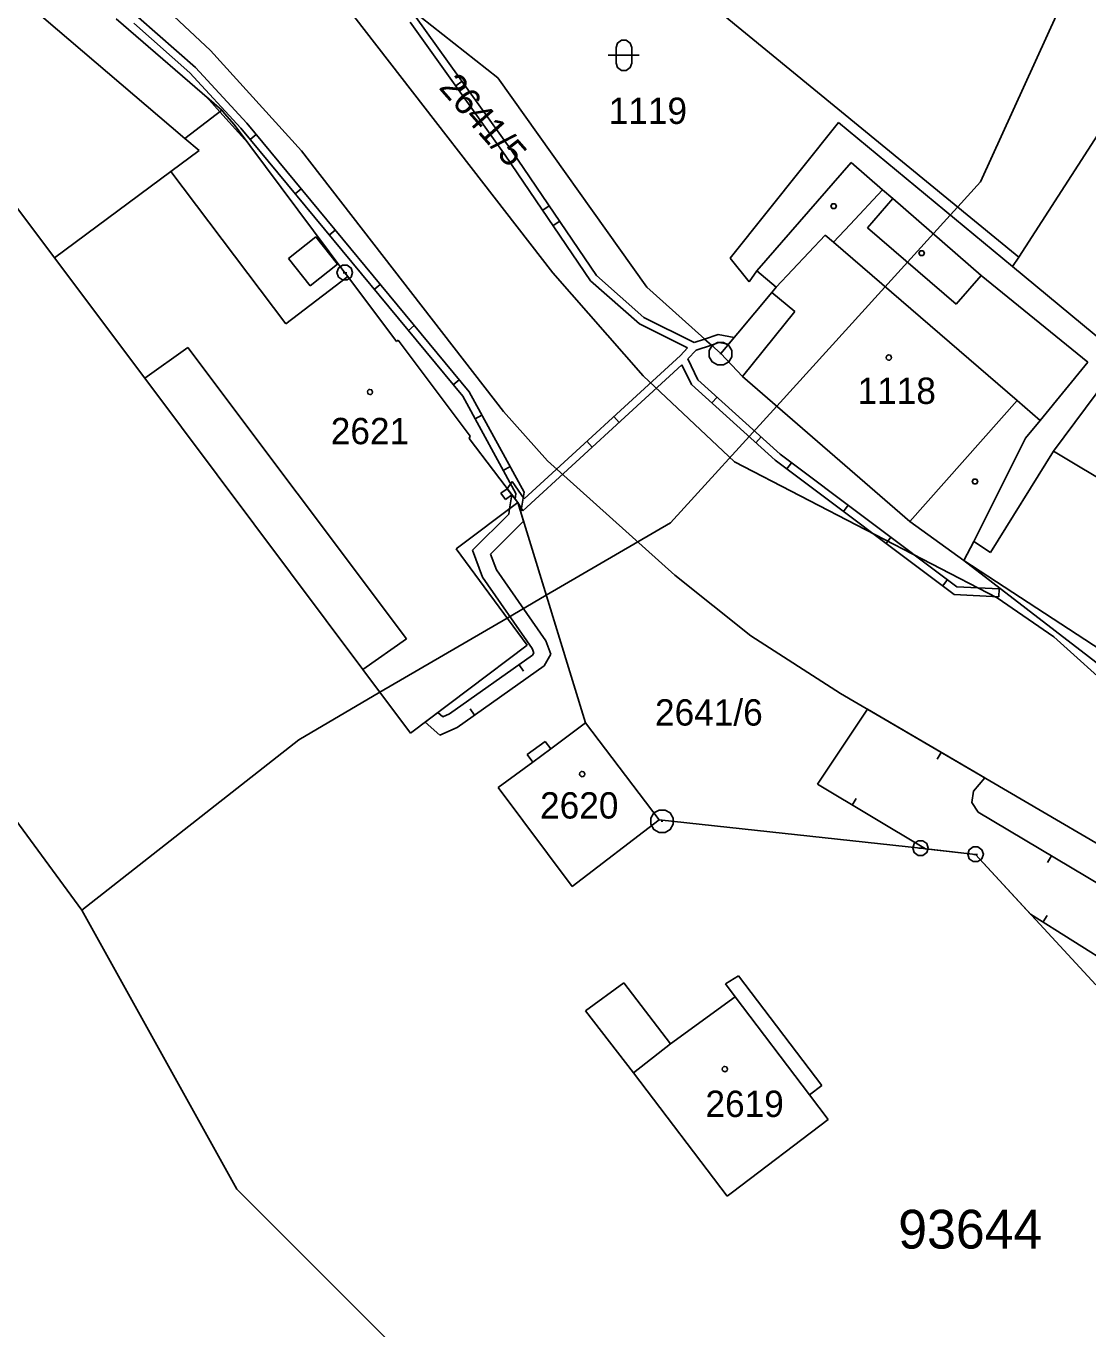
# Model space of a CAD drawing. Extents: x -806774 to -803680, y -1151731 to -1150053.
# Drawn here: x -804078.6 to -804010.1, y -1150277.5 to -1150193.4 of the extents above; entities that cross this region are included whole.
import ezdxf

# ---------------------------------------------------------------- set-up
doc = ezdxf.new("R2010")
doc.units = 0
for name, color, linetype in [('1', 7, 'Continuous'), ('11', 7, 'Continuous'), ('12', 7, 'Continuous'), ('13', 7, 'Continuous'), ('2', 7, 'Continuous'), ('3', 7, 'Continuous'), ('4', 7, 'Continuous'), ('5', 7, 'Continuous'), ('8', 7, 'Continuous')]:
    doc.layers.add(name, color=color, linetype=linetype)

msp = doc.modelspace()

# ---------------------------------------------------------------- linework, layer by layer
at = {"layer": '1'}
for p, q in [((-804038.18, -1150188.96), (-804014.54, -1150208.35)), ((-804079.56, -1150191.12), (-804068.34, -1150200.69)), ((-804066.7, -1150195.01), (-804070.61, -1150191.34)), ((-804054.55, -1150191.72), (-804048.14, -1150196.79)), ((-804065.96, -1150198.88), (-804072.79, -1150192.97)), ((-804057.45, -1150192.8), (-804044.6, -1150209.37)), ((-804005.52, -1150194.37), (-804014.54, -1150208.35)), ((-804060.81, -1150201.5), (-804066.7, -1150195.01)), ((-804048.14, -1150196.79), (-804038.53, -1150210.29)), ((-804068.34, -1150200.69), (-804065.96, -1150198.88)), ((-804065.78, -1150199.08), (-804065.96, -1150198.88)), ((-804065.78, -1150199.08), (-804065.16, -1150199.8)), ((-804065.16, -1150199.8), (-804058.02, -1150209.36)), ((-804033.15, -1150208.42), (-804026.17, -1150199.66)), ((-804026.17, -1150199.66), (-804014.94, -1150208.97)), ((-804082.27, -1150201.05), (-804076.76, -1150208.41)), ((-804067.42, -1150201.47), (-804068.34, -1150200.69)), ((-804069.26, -1150202.82), (-804067.42, -1150201.47)), ((-804047.79, -1150218.32), (-804060.81, -1150201.5)), ((-804076.76, -1150208.41), (-804069.26, -1150202.82)), ((-804070.92, -1150216.16), (-804076.76, -1150208.41)), ((-804031.94, -1150209.94), (-804033.15, -1150208.42)), ((-804014.94, -1150208.97), (-804014.54, -1150208.35)), ((-804058.02, -1150209.36), (-804057.84, -1150209.6)), ((-804057.84, -1150209.6), (-804054.7, -1150213.8)), ((-804044.6, -1150209.37), (-804038.78, -1150216.01)), ((-804031.44, -1150209.25), (-804031.94, -1150209.94)), ((-804030.19, -1150210.3), (-804031.44, -1150209.25)), ((-804014.94, -1150208.97), (-804007.83, -1150214.86)), ((-804038.53, -1150210.29), (-804033.76, -1150214.58)), ((-804030.19, -1150210.3), (-804030.47, -1150210.63)), ((-804033.76, -1150214.58), (-804030.47, -1150210.63)), ((-804054.7, -1150213.8), (-804054.58, -1150213.71)), ((-804054.58, -1150213.71), (-804049.93, -1150219.91)), ((-804033.76, -1150214.58), (-804032.36, -1150216.05)), ((-804007.83, -1150214.86), (-804012.29, -1150220.87)), ((-804056.87, -1150234.96), (-804070.92, -1150216.16)), ((-804038.78, -1150216.01), (-804032.88, -1150221.57)), ((-804021.57, -1150225.42), (-804032.36, -1150216.05)), ((-804044.95, -1150221.51), (-804047.79, -1150218.32)), ((-804049.93, -1150219.91), (-804050.01, -1150220.06)), ((-804050.01, -1150220.06), (-804046.86, -1150224.2)), ((-804012.29, -1150220.87), (-804016.36, -1150227.42)), ((-803996.21, -1150230.54), (-804012.29, -1150220.87)), ((-804036.73, -1150228.89), (-804044.95, -1150221.51)), ((-804032.88, -1150221.57), (-804015.93, -1150230.34)), ((-804050.84, -1150227.18), (-804046.86, -1150224.2)), ((-804046.86, -1150224.2), (-804042.5, -1150238.42)), ((-804021.57, -1150225.42), (-804018.08, -1150227.93)), ((-804046.26, -1150233.41), (-804050.84, -1150227.18)), ((-804018.08, -1150227.93), (-804017.43, -1150226.7)), ((-804017.43, -1150226.7), (-804016.36, -1150227.42)), ((-804002.08, -1150240.27), (-804018.08, -1150227.93)), ((-804031.83, -1150232.79), (-804036.73, -1150228.89)), ((-804015.93, -1150230.34), (-804012.27, -1150232.87)), ((-804026.04, -1150236.52), (-804031.83, -1150232.79)), ((-804012.27, -1150232.87), (-804002.98, -1150241.24)), ((-804053.79, -1150239.08), (-804046.26, -1150233.41)), ((-804053.79, -1150239.08), (-804056.87, -1150234.96)), ((-804001.67, -1150250.78), (-804026.04, -1150236.52)), ((-804042.5, -1150238.42), (-804044.74, -1150240.08)), ((-804042.5, -1150238.42), (-804037.73, -1150244.68)), ((-804045.09, -1150239.61), (-804046.26, -1150240.46)), ((-804044.74, -1150240.08), (-804045.09, -1150239.61)), ((-804046.26, -1150240.46), (-804045.9, -1150240.94)), ((-804045.9, -1150240.94), (-804048.13, -1150242.59)), ((-804043.35, -1150248.97), (-804048.13, -1150242.59)), ((-804037.73, -1150244.68), (-804043.35, -1150248.97)), ((-804020.87, -1150246.51), (-804037.73, -1150244.68)), ((-804017.32, -1150246.9), (-804020.87, -1150246.51)), ((-804017.32, -1150246.9), (-804009.55, -1150255.32)), ((-804033.46, -1150255.26), (-804032.63, -1150254.75)), ((-804032.63, -1150254.75), (-804027.25, -1150261.82)), ((-804042.49, -1150256.99), (-804040.01, -1150255.2)), ((-804040.01, -1150255.2), (-804037.01, -1150259.13)), ((-804032.83, -1150256.09), (-804033.46, -1150255.26)), ((-804037.01, -1150259.13), (-804032.83, -1150256.09)), ((-804039.39, -1150261.01), (-804042.49, -1150256.99)), ((-804033.36, -1150268.97), (-804039.39, -1150261.01)), ((-804028.04, -1150262.42), (-804027.25, -1150261.82)), ((-804026.84, -1150264.01), (-804028.04, -1150262.42)), ((-804033, -1150268.7), (-804026.84, -1150264.01)), ((-804033, -1150268.7), (-804033.36, -1150268.97))]:
    msp.add_line(p, q, dxfattribs=at)
at = {"layer": '11'}
for points in [[(-804075, -1150250.5), (-804061, -1150239.5), (-804055.76, -1150236.44), (-804047.55, -1150231.65), (-804045.03, -1150230.18), (-804037, -1150225.5), (-804030.15, -1150217.97), (-804018.95, -1150205.65), (-804018.47, -1150205.12), (-804017, -1150203.5), (-804007.8, -1150183.27), (-804007, -1150181.5), (-804006.2, -1150179.38), (-804002.16, -1150168.59), (-804001.72, -1150167.41), (-804001, -1150165.5), (-803996.39, -1150161.1), (-803995.83, -1150160.56), (-803991.51, -1150156.45), (-803989.423, -1150154.449)], [(-804075, -1150250.5), (-804130.24, -1150175.18), (-804140.05, -1150161.79), (-804142.886, -1150157.919)], [(-804025, -1150309.5), (-804033, -1150300.5), (-804065, -1150268.5), (-804075, -1150250.5)]]:
    msp.add_lwpolyline(points, dxfattribs=at)
at = {"layer": '12'}
for p, q in [((-804076.76, -1150208.41), (-804069.26, -1150202.82)), ((-804069.26, -1150202.82), (-804061.84, -1150212.67)), ((-804030.19, -1150210.3), (-804027.02, -1150206.93)), ((-804027.02, -1150206.93), (-804026.48, -1150207.39)), ((-804026.48, -1150207.39), (-804014.63, -1150217.6)), ((-804070.92, -1150216.16), (-804076.76, -1150208.41)), ((-804061.84, -1150212.67), (-804057.84, -1150209.6)), ((-804057.84, -1150209.6), (-804054.7, -1150213.8)), ((-804030.19, -1150210.3), (-804030.47, -1150210.63)), ((-804030.47, -1150210.63), (-804028.99, -1150211.86)), ((-804028.99, -1150211.86), (-804032.36, -1150216.05)), ((-804054.7, -1150213.8), (-804054.58, -1150213.71)), ((-804054.58, -1150213.71), (-804049.93, -1150219.91)), ((-804070.92, -1150216.16), (-804068.15, -1150214.19)), ((-804068.15, -1150214.19), (-804054.05, -1150233)), ((-804021.57, -1150225.42), (-804032.36, -1150216.05)), ((-804021.57, -1150225.42), (-804014.63, -1150217.6)), ((-804049.93, -1150219.91), (-804050.01, -1150220.06)), ((-804050.01, -1150220.06), (-804046.86, -1150224.2)), ((-804050.84, -1150227.18), (-804046.86, -1150224.2)), ((-804046.26, -1150233.41), (-804050.84, -1150227.18)), ((-804054.05, -1150233), (-804056.87, -1150234.96)), ((-804053.79, -1150239.08), (-804046.26, -1150233.41)), ((-804053.79, -1150239.08), (-804056.87, -1150234.96)), ((-804042.5, -1150238.42), (-804044.74, -1150240.08)), ((-804042.5, -1150238.42), (-804037.73, -1150244.68)), ((-804044.74, -1150240.08), (-804045.9, -1150240.94)), ((-804045.9, -1150240.94), (-804048.13, -1150242.59)), ((-804043.35, -1150248.97), (-804048.13, -1150242.59)), ((-804037.73, -1150244.68), (-804043.35, -1150248.97)), ((-804037.01, -1150259.13), (-804032.83, -1150256.09)), ((-804032.83, -1150256.09), (-804028.04, -1150262.42)), ((-804039.39, -1150261.01), (-804037.01, -1150259.13)), ((-804033.36, -1150268.97), (-804039.39, -1150261.01)), ((-804026.84, -1150264.01), (-804028.04, -1150262.42)), ((-804033, -1150268.7), (-804026.84, -1150264.01)), ((-804033, -1150268.7), (-804033.36, -1150268.97))]:
    msp.add_line(p, q, dxfattribs=at)
at = {"layer": '13'}
for p, q in [((-804068.02, -1150196.47), (-804071.65, -1150193.26)), ((-804071.33, -1150192.88), (-804067.66, -1150196.11)), ((-804047.67, -1150201.77), (-804053.8, -1150193.2)), ((-804053.42, -1150192.88), (-804047.25, -1150201.49)), ((-804067.66, -1150196.11), (-804064.35, -1150199.72)), ((-804064.73, -1150200.03), (-804068.02, -1150196.47)), ((-804050.87, -1150197.297), (-804050.463, -1150197.006)), ((-804050.216, -1150197.351), (-804050.623, -1150197.642)), ((-804066.96, -1150198.01), (-804065.96, -1150198.88)), ((-804066.09, -1150198.98), (-804066.96, -1150198.01)), ((-804064.28, -1150200.98), (-804066.09, -1150198.98)), ((-804065.96, -1150198.88), (-804065.78, -1150199.08)), ((-804065.78, -1150199.08), (-804065.16, -1150199.8)), ((-804065.16, -1150199.8), (-804064.28, -1150200.98)), ((-804050.42, -1150217.33), (-804064.73, -1150200.03)), ((-804064.35, -1150199.72), (-804050, -1150217.05)), ((-804064.124, -1150200.763), (-804063.738, -1150200.444)), ((-804042.16, -1150209.88), (-804047.67, -1150201.77)), ((-804047.25, -1150201.49), (-804041.78, -1150209.54)), ((-804060.842, -1150203.956), (-804061.227, -1150204.275)), ((-804045.251, -1150205.331), (-804044.837, -1150205.049)), ((-804044.159, -1150206.039), (-804044.572, -1150206.32)), ((-804059.025, -1150206.928), (-804058.639, -1150206.609)), ((-804041.78, -1150209.54), (-804038.72, -1150212.25)), ((-804055.74, -1150210.118), (-804056.125, -1150210.437)), ((-804039, -1150212.67), (-804042.16, -1150209.88)), ((-804053.926, -1150213.092), (-804053.54, -1150212.773)), ((-804035.91, -1150214.21), (-804039, -1150212.67)), ((-804038.72, -1150212.25), (-804035.48, -1150213.86)), ((-804035.48, -1150213.86), (-804034.81, -1150213.64)), ((-804034.81, -1150213.64), (-804033.93, -1150213.35)), ((-804034.81, -1150213.64), (-804034.37, -1150214.03)), ((-804034.37, -1150214.03), (-804034.81, -1150213.64)), ((-804033.93, -1150213.35), (-804032.9, -1150213.54)), ((-804032.9, -1150213.54), (-804033.26, -1150213.98)), ((-804036.37, -1150214.71), (-804035.91, -1150214.21)), ((-804035.36, -1150214.35), (-804035.89, -1150214.93)), ((-804034.37, -1150214.03), (-804035.36, -1150214.35)), ((-804033.89, -1150213.87), (-804034.37, -1150214.03)), ((-804033.26, -1150213.98), (-804033.89, -1150213.87)), ((-804036.27, -1150215.3), (-804046.53, -1150224.72)), ((-804046.45, -1150223.96), (-804036.37, -1150214.71)), ((-804035.65, -1150216.58), (-804036.27, -1150215.3)), ((-804035.89, -1150214.93), (-804035.25, -1150216.28)), ((-804050.638, -1150216.28), (-804051.023, -1150216.599)), ((-804035.25, -1150216.28), (-804029.94, -1150221.07)), ((-804050, -1150217.05), (-804046.46, -1150223.53)), ((-804030.26, -1150221.45), (-804035.65, -1150216.58)), ((-804046.98, -1150223.61), (-804050.42, -1150217.33)), ((-804034.341, -1150217.763), (-804034.006, -1150217.392)), ((-804049.622, -1150218.786), (-804049.184, -1150218.546)), ((-804040.321, -1150219.02), (-804040.659, -1150218.651)), ((-804042.398, -1150220.241), (-804042.06, -1150220.61)), ((-804031.166, -1150219.964), (-804031.501, -1150220.335)), ((-804029.94, -1150221.07), (-804018.52, -1150229.63)), ((-804047.363, -1150221.877), (-804047.802, -1150222.116)), ((-804018.7, -1150230.13), (-804030.26, -1150221.45)), ((-804029.496, -1150222.024), (-804029.195, -1150221.624)), ((-804047.55, -1150223.3), (-804047.23, -1150222.84)), ((-804047.23, -1150222.84), (-804046.45, -1150223.96)), ((-804047.95, -1150223.6), (-804047.55, -1150223.3)), ((-804047.65, -1150224), (-804047.95, -1150223.6)), ((-804047.25, -1150223.69), (-804047.65, -1150224)), ((-804047.25, -1150223.69), (-804047.55, -1150223.3)), ((-804047.55, -1150223.3), (-804047.25, -1150223.69)), ((-804047.39, -1150224.6), (-804047.25, -1150223.69)), ((-804046.86, -1150224.2), (-804047.25, -1150223.69)), ((-804047.25, -1150223.69), (-804046.86, -1150224.2)), ((-804047.04, -1150223.97), (-804046.98, -1150223.61)), ((-804046.46, -1150223.53), (-804046.67, -1150224.82)), ((-804047.45, -1150224.94), (-804047.39, -1150224.6)), ((-804046.86, -1150224.2), (-804047.04, -1150223.97)), ((-804046.53, -1150224.72), (-804046.86, -1150224.2)), ((-804046.67, -1150224.82), (-804046.86, -1150224.2)), ((-804046.86, -1150224.2), (-804046.49, -1150225.4)), ((-804025.539, -1150224.369), (-804025.839, -1150224.769)), ((-804049.79, -1150227.26), (-804047.45, -1150224.94)), ((-804046.49, -1150225.4), (-804048.63, -1150227.52)), ((-804023.098, -1150226.828), (-804022.798, -1150226.428)), ((-804049.13, -1150229), (-804049.79, -1150227.26)), ((-804048.63, -1150227.52), (-804048.24, -1150228.53)), ((-804048.24, -1150228.53), (-804045.05, -1150233.13)), ((-804045.93, -1150233.61), (-804049.13, -1150229)), ((-804019.138, -1150229.167), (-804019.438, -1150229.567)), ((-804018.52, -1150229.63), (-804015.79, -1150229.77)), ((-804015.79, -1150229.77), (-804015.81, -1150230.27)), ((-804015.81, -1150230.27), (-804018.7, -1150230.13)), ((-804045.05, -1150233.13), (-804044.72, -1150233.98)), ((-804045.82, -1150233.9), (-804045.93, -1150233.61)), ((-804045.91, -1150234.04), (-804045.82, -1150233.9)), ((-804044.72, -1150233.98), (-804045.17, -1150234.74)), ((-804051.27, -1150237.84), (-804045.91, -1150234.04)), ((-804045.17, -1150234.74), (-804050.77, -1150238.72)), ((-804046.783, -1150234.659), (-804046.494, -1150235.067)), ((-804051.69, -1150238.03), (-804051.27, -1150237.84)), ((-804049.653, -1150237.926), (-804049.943, -1150237.519)), ((-804027.53, -1150242.37), (-804024.29, -1150237.54)), ((-804024.29, -1150237.54), (-804016.73, -1150241.97)), ((-804051.89, -1150239.2), (-804052.83, -1150238.36)), ((-804050.77, -1150238.72), (-804051.89, -1150239.2)), ((-804019.545, -1150240.321), (-804019.798, -1150240.752)), ((-804020.56, -1150246.54), (-804027.53, -1150242.37)), ((-804016.73, -1150241.97), (-804017.45, -1150242.82)), ((-804017.45, -1150242.82), (-804017.57, -1150243.55)), ((-804025.28, -1150243.716), (-804025.023, -1150243.287)), ((-804017.57, -1150243.55), (-804017.15, -1150244.18)), ((-804017.15, -1150244.18), (-804008.16, -1150249.55)), ((-804017.32, -1150246.9), (-804020.56, -1150246.54)), ((-804013.77, -1150250.75), (-804017.32, -1150246.9)), ((-804012.428, -1150247), (-804012.685, -1150247.43)), ((-804008.32, -1150254.2), (-804013.77, -1150250.75)), ((-804012.967, -1150251.258), (-804012.7, -1150250.836))]:
    msp.add_line(p, q, dxfattribs=at)
msp.add_lwpolyline([(-804052.83, -1150238.36), (-804052.02, -1150237.75), (-804051.69, -1150238.03)], dxfattribs=at)
at = {"layer": '3'}
msp.add_lwpolyline([(-804040.52, -1150194.83), (-804040.42, -1150194.54), (-804040.17, -1150194.36), (-804039.86, -1150194.36), (-804039.61, -1150194.54), (-804039.51, -1150194.83), (-804039.51, -1150195.83), (-804039.61, -1150196.12), (-804039.86, -1150196.3), (-804040.17, -1150196.3), (-804040.42, -1150196.12), (-804040.52, -1150195.83)], close=True, dxfattribs=at)
msp.add_lwpolyline([(-804041.02, -1150195.33), (-804039.75, -1150195.33), (-804039.02, -1150195.33)], dxfattribs=at)
at = {"layer": '4'}
for p, q in [((-804069.26, -1150202.82), (-804061.84, -1150212.67)), ((-804031.44, -1150209.25), (-804025.36, -1150202.24)), ((-804025.36, -1150202.24), (-804023.32, -1150204.02)), ((-804025.41, -1150206.25), (-804023.32, -1150204.02)), ((-804023.32, -1150204.02), (-804022.66, -1150204.58)), ((-804024.3, -1150206.46), (-804022.66, -1150204.58)), ((-804022.66, -1150204.58), (-804016.95, -1150209.55)), ((-804026.48, -1150207.39), (-804025.41, -1150206.25)), ((-804059.9, -1150207.04), (-804061.67, -1150208.45)), ((-804059.9, -1150207.04), (-804058.5, -1150208.8)), ((-804030.19, -1150210.3), (-804027.02, -1150206.93)), ((-804027.02, -1150206.93), (-804026.48, -1150207.39)), ((-804018.57, -1150211.4), (-804024.3, -1150206.46)), ((-804026.48, -1150207.39), (-804014.63, -1150217.6)), ((-804060.27, -1150210.21), (-804061.67, -1150208.45)), ((-804061.84, -1150212.67), (-804057.84, -1150209.6)), ((-804058.5, -1150208.8), (-804060.27, -1150210.21)), ((-804018.57, -1150211.4), (-804016.95, -1150209.55)), ((-804016.95, -1150209.55), (-804010.08, -1150215.13)), ((-804030.47, -1150210.63), (-804028.99, -1150211.86)), ((-804028.99, -1150211.86), (-804032.36, -1150216.05)), ((-804070.92, -1150216.16), (-804068.15, -1150214.19)), ((-804068.15, -1150214.19), (-804054.05, -1150233)), ((-804013.16, -1150218.89), (-804010.08, -1150215.13)), ((-804021.57, -1150225.42), (-804014.63, -1150217.6)), ((-804014.63, -1150217.6), (-804013.16, -1150218.89)), ((-804013.16, -1150218.89), (-804014.1, -1150220.04)), ((-804017.43, -1150226.7), (-804014.1, -1150220.04)), ((-804001.25, -1150238.93), (-804018.08, -1150227.93)), ((-804054.05, -1150233), (-804056.87, -1150234.96)), ((-804044.74, -1150240.08), (-804045.9, -1150240.94)), ((-804032.83, -1150256.09), (-804028.04, -1150262.42)), ((-804039.39, -1150261.01), (-804037.01, -1150259.13))]:
    msp.add_line(p, q, dxfattribs=at)
at = {"layer": '5'}
for points in [[(-804026.39, -1150204.91), (-804026.3, -1150205.06), (-804026.39, -1150205.21), (-804026.57, -1150205.21), (-804026.66, -1150205.06), (-804026.57, -1150204.91)], [(-804020.71, -1150207.95), (-804020.62, -1150208.1), (-804020.71, -1150208.25), (-804020.89, -1150208.25), (-804020.98, -1150208.1), (-804020.89, -1150207.95)], [(-804022.92, -1150214.67), (-804022.82, -1150214.69), (-804022.77, -1150214.78), (-804022.75, -1150214.84), (-804022.77, -1150214.93), (-804022.85, -1150215), (-804022.92, -1150215.01), (-804023.01, -1150214.98), (-804023.07, -1150214.92), (-804023.09, -1150214.84), (-804023.07, -1150214.75), (-804022.99, -1150214.68)], [(-804056.4, -1150216.89), (-804056.3, -1150216.91), (-804056.25, -1150217), (-804056.23, -1150217.06), (-804056.25, -1150217.15), (-804056.33, -1150217.22), (-804056.4, -1150217.23), (-804056.49, -1150217.2), (-804056.55, -1150217.14), (-804056.57, -1150217.06), (-804056.55, -1150216.97), (-804056.47, -1150216.9)], [(-804017.27, -1150222.68), (-804017.18, -1150222.83), (-804017.27, -1150222.98), (-804017.45, -1150222.98), (-804017.54, -1150222.83), (-804017.45, -1150222.68)], [(-804042.71, -1150241.55), (-804042.61, -1150241.57), (-804042.56, -1150241.66), (-804042.54, -1150241.72), (-804042.56, -1150241.81), (-804042.64, -1150241.88), (-804042.71, -1150241.89), (-804042.8, -1150241.86), (-804042.86, -1150241.8), (-804042.88, -1150241.72), (-804042.86, -1150241.63), (-804042.78, -1150241.56)], [(-804033.5, -1150260.59), (-804033.4, -1150260.61), (-804033.35, -1150260.7), (-804033.33, -1150260.76), (-804033.35, -1150260.85), (-804033.43, -1150260.92), (-804033.5, -1150260.93), (-804033.59, -1150260.9), (-804033.65, -1150260.84), (-804033.67, -1150260.76), (-804033.65, -1150260.67), (-804033.57, -1150260.6)]]:
    msp.add_lwpolyline(points, close=True, dxfattribs=at)
at = {"layer": '8'}
for p, q in [((-804058.14, -1150209.36), (-804057.9, -1150209.36)), ((-804033.83, -1150214.58), (-804033.73, -1150214.58)), ((-804037.6, -1150244.76), (-804037.5, -1150244.76)), ((-804020.99, -1150246.51), (-804020.75, -1150246.51)), ((-804017.44, -1150246.9), (-804017.2, -1150246.9))]:
    msp.add_line(p, q, dxfattribs=at)
for points in [[(-804057.87, -1150208.88), (-804057.62, -1150209.06), (-804057.52, -1150209.35), (-804057.62, -1150209.64), (-804057.87, -1150209.82), (-804058.18, -1150209.82), (-804058.43, -1150209.64), (-804058.53, -1150209.35), (-804058.43, -1150209.06), (-804058.18, -1150208.88)], [(-804033.59, -1150213.86), (-804033.25, -1150214.05), (-804033.06, -1150214.39), (-804033.06, -1150214.78), (-804033.25, -1150215.12), (-804033.59, -1150215.31), (-804033.98, -1150215.31), (-804034.32, -1150215.12), (-804034.51, -1150214.78), (-804034.51, -1150214.39), (-804034.32, -1150214.05), (-804033.98, -1150213.86)], [(-804037.36, -1150244.04), (-804037.02, -1150244.23), (-804036.83, -1150244.57), (-804036.83, -1150244.96), (-804037.02, -1150245.3), (-804037.36, -1150245.49), (-804037.75, -1150245.49), (-804038.09, -1150245.3), (-804038.28, -1150244.96), (-804038.28, -1150244.57), (-804038.09, -1150244.23), (-804037.75, -1150244.04)], [(-804020.72, -1150246.03), (-804020.47, -1150246.21), (-804020.37, -1150246.5), (-804020.47, -1150246.79), (-804020.72, -1150246.97), (-804021.03, -1150246.97), (-804021.28, -1150246.79), (-804021.38, -1150246.5), (-804021.28, -1150246.21), (-804021.03, -1150246.03)], [(-804017.17, -1150246.42), (-804016.92, -1150246.6), (-804016.82, -1150246.89), (-804016.92, -1150247.18), (-804017.17, -1150247.36), (-804017.48, -1150247.36), (-804017.73, -1150247.18), (-804017.83, -1150246.89), (-804017.73, -1150246.6), (-804017.48, -1150246.42)]]:
    msp.add_lwpolyline(points, close=True, dxfattribs=at)

# ---------------------------------------------------------------- texts
at = {"layer": '11'}
msp.add_text('93644', height=2.5, dxfattribs=at).set_placement((-804022.312, -1150272.342))
at = {"layer": '2'}
msp.add_text('2641/5', height=1.7, rotation=311.40256, dxfattribs=at).set_placement((-804052.016, -1150197.438))
for s, p in [('1119', (-804040.997, -1150199.76)), ('1118', (-804024.939, -1150217.83)), ('2621', (-804058.933, -1150220.43)), ('2641/6', (-804038.008, -1150238.59)), ('2620', (-804045.427, -1150244.59)), ('2619', (-804034.753, -1150263.85))]:
    msp.add_text(s, height=1.7, dxfattribs=at).set_placement(p)

doc.saveas('drawing.dxf')
